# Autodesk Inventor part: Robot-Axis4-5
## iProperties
Shininess: 21.0
Length Units: 11269
Angle Units: 11279
Time Units: 11290
Mass Units: 11283
Length Display Precision: 3
Angle Display Precision: 2
Created: 2001-08
Part Number: Robot-Axis4-5
Document SubType Name: ﾓﾃﾞﾘﾝｸﾞ
Designer: Administrator
Density: 1 g/cm^3
Density: 0.0
Volumn: 0.0
Area: 0.0
PropertySet Name: Model Information
Control State: 0
Master: False
Checked Out: False
Author: Administrator
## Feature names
1. 押し出し1 [Extrusion]
2. 押し出し2 [Extrusion]
3. Fillet1
4. 押し出し3 [Extrusion]
5. Shell1
6. Hole1
7. Hole2
8. Hole3
